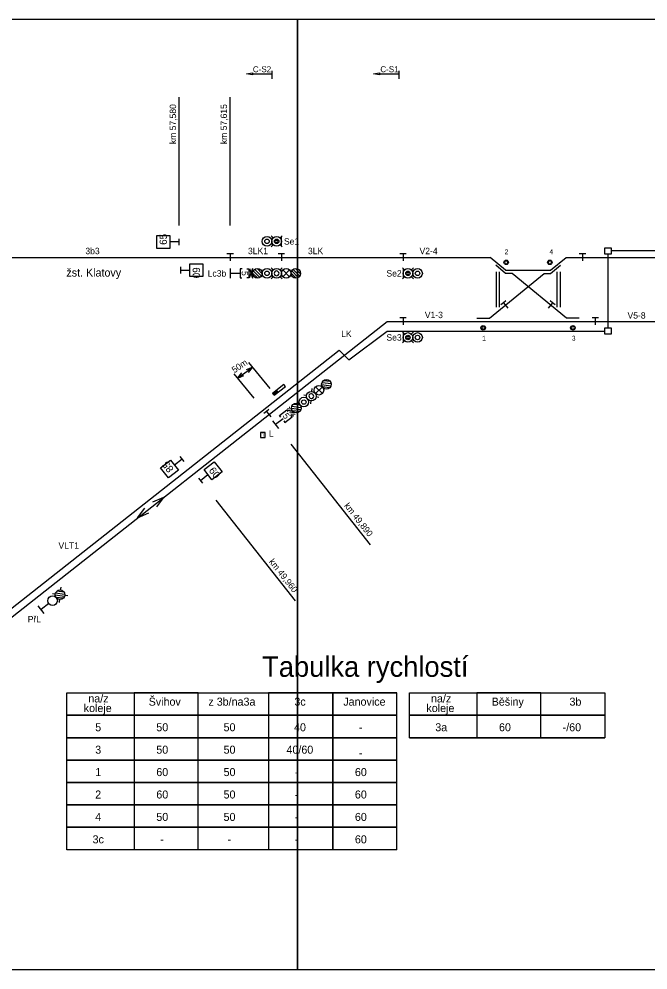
# Model space of a CAD drawing. Extents: x -1146 to 534, y 4 to 301.
# Drawn here: x -602.9 to -406.6, y 4.4 to 301.4 of the extents above; entities that cross this region are included whole.
import ezdxf

# ---------------------------------------------------------------- set-up
doc = ezdxf.new("R2010")
doc.units = 0
for name, color, linetype in [('1', 7, 'Continuous'), ('formát tisku', 7, 'Continuous'), ('kabel', 7, 'Continuous'), ('koleje', 7, 'Continuous'), ('návěstidla', 7, 'Continuous'), ('POPIS', 7, 'Continuous'), ('popisy', 7, 'Continuous'), ('čd', 7, 'Continuous')]:
    doc.layers.add(name, color=color, linetype=linetype)

# ---------------------------------------------------------------- blocks, each defined once
blk = doc.blocks.new('SB1')
for p, q in [((0, 1.08), (-1, 1.08)), ((1, 1.08), (0, 1.08)), ((0, 1.08), (0, -1.08))]:
    blk.add_line(p, q)
blk = doc.blocks.new('NS1')
for p, q in [((-1, 2.5), (-1.7, 3.2)), ((1, 2.5), (1.7, 3.2)), ((-1, 0.5), (-1.7, -0.2)), ((-1.5, 0), (1.5, 0)), ((1, 0.5), (1.7, -0.2))]:
    blk.add_line(p, q)
for centre, radius in [((0, 4.5), 1.5), ((0, 1.5), 1.5), ((0, 4.5), 0.7)]:
    blk.add_circle(centre, radius)
for start, end in [(0, 180), (180, 0)]:
    blk.add_arc((0, 1.5), 0.375, start, end)
blk = doc.blocks.new('NS16')
for p, q in [((-1.499, 0.6437), (-1.1298, 1.0129)), ((-1.4356, 0), (-0.4227, 1.0129)), ((-0.7285, 0), (0.2844, 1.0129)), ((-0.0214, 0), (0.9915, 1.0129)), ((0.6857, 0), (1.499, 0.8133)), ((1.3928, 0), (1.499, 0.1062))]:
    blk.add_line(p, q)
blk = doc.blocks.new('U10')
at = {"layer": '1'}
for p, q in [((-6.9999, -2), (-6.9999, 2)), ((-6.9999, 2), (-3, 2)), ((-3, 2), (-3, -2)), ((0, 0), (-3, 0)), ((0, -1), (0, 1)), ((-3, -2), (-6.9999, -2))]:
    blk.add_line(p, q, dxfattribs=at)
blk = doc.blocks.new('O9')
for p, q in [((-1.5, 3), (-1.5, 0)), ((1.5, 3), (-1.5, 3)), ((-1.5, 0), (1.5, 0)), ((1.5, 0), (1.5, 3))]:
    blk.add_line(p, q)
blk.add_text('T', height=2).set_placement((-0.68, 0.41))
blk = doc.blocks.new('_X11')
for p, q in [((-0.5, 5.16), (0.34, 6)), ((-0.5, 5.33), (0.17, 6)), ((-0.5, 5.51), (-0.01, 6)), ((-0.5, 5.69), (-0.19, 6)), ((-0.5, 5.86), (-0.36, 6)), ((-0.5, 4.98), (0.5, 5.98)), ((-0.5, 4.8), (0.5, 5.8)), ((-0.5, 4.63), (0.5, 5.63)), ((-0.5, 4.45), (0.5, 5.45)), ((-0.5, 4.27), (0.5, 5.27)), ((-0.5, 4.1), (0.5, 5.1)), ((-0.42, 4), (0.5, 4.92)), ((-0.24, 4), (0.5, 4.74)), ((-0.07, 4), (0.5, 4.57)), ((0.11, 4), (0.5, 4.39)), ((0.29, 4), (0.5, 4.21)), ((0.46, 4), (0.5, 4.04))]:
    blk.add_line(p, q)
blk = doc.blocks.new('PZ15')
for p, q in [((0.5, 6), (-0.5, 6)), ((-0.5, 6), (-0.5, 0)), ((0.5, 0), (0.5, 6)), ((-0.5, 0), (0.5, 0))]:
    blk.add_line(p, q)
blk.add_lwpolyline([(0.5, 6), (0.5, 4), (-0.5, 4), (-0.5, 6)], close=True)
blk.add_lwpolyline([(-0.5, 6), (0.5, 6), (0.5, 4), (-0.5, 4), (-0.5, 6)])
blk.add_blockref('_X11', (0, 0))
blk = doc.blocks.new('PZ2')
for start, end in [(0, 180), (180, 0)]:
    blk.add_arc((0, 2), 0.5, start, end)

msp = doc.modelspace()

# ---------------------------------------------------------------- linework, layer by layer
for p, q in [((-515.96, 301.44), (-515.96, 292.56)), ((-537, 223.5), (-537, 220.5)), ((-527.75, 220.7), (-529.8, 222.8)), ((-527.3, 221.2), (-529.3, 223.2)), ((-527, 221.9), (-528.6, 223.5)), ((-523.5, 223), (-524.2, 223.7)), ((-521.5, 223), (-520.8, 223.7)), ((-515.75, 220.7), (-517.78, 222.78)), ((-515.26, 221.16), (-517.34, 223.24)), ((-515, 221.9), (-516.6, 223.5)), ((-534, 222), (-537, 222)), ((-528.4, 220.5), (-530, 222.1)), ((-523.5, 221), (-524.2, 220.3)), ((-521.5, 221), (-520.8, 220.3)), ((-516.4, 220.5), (-518, 222.1)), ((-534.6, 189.34), (-533.37, 190.96)), ((-534.59, 189.32), (-532.73, 190.15)), ((-530.12, 192.64), (-532.02, 191.91)), ((-530.11, 192.63), (-531.43, 191.07)), ((-505.55, 186.82), (-508.46, 187.2)), ((-505.51, 187.49), (-508.31, 187.82)), ((-505.7, 188.22), (-507.95, 188.49)), ((-511.49, 185.07), (-511.37, 186.05)), ((-505.94, 186.26), (-508.18, 186.53)), ((-513.06, 183.83), (-514.04, 183.95)), ((-511.82, 182.26), (-511.94, 181.28)), ((-510.25, 183.5), (-509.27, 183.38)), ((-514.98, 179.39), (-517.89, 179.78)), ((-514.93, 180.06), (-517.74, 180.4)), ((-515.36, 178.83), (-517.61, 179.1)), ((-515.13, 180.8), (-517.38, 181.07)), ((-523.74, 175.95), (-521.89, 173.59)), ((-520.46, 176.62), (-522.82, 174.77)), ((-557.77, 152.06), (-561.21, 150.56)), ((-557.77, 152.06), (-560.04, 149.07)), ((-565.89, 145.67), (-563.62, 148.66)), ((-565.89, 145.67), (-562.45, 147.17)), ((-591.51, 121.81), (-592.49, 121.92)), ((-588.68, 121.76), (-591.49, 122.09)), ((-588.88, 122.49), (-591.13, 122.76)), ((-589.94, 123.04), (-589.82, 124.03)), ((-593.64, 118.86), (-596, 117)), ((-588.73, 121.09), (-591.64, 121.47)), ((-589.11, 120.53), (-591.36, 120.8)), ((-590.27, 120.24), (-590.39, 119.25)), ((-588.7, 121.47), (-587.72, 121.36)), ((-595.07, 115.82), (-596.93, 118.18)), ((-515.96, 4.44), (-515.96, 13.33))]:
    msp.add_line(p, q)
for centre, radius in [((-522.5, 232), 0.7), ((-450.81, 225.44), 0.7), ((-437.19, 225.44), 0.7), ((-528.5, 222), 1.5), ((-525.5, 222), 1.5), ((-522.5, 222), 1.5), ((-519.5, 222), 1.5), ((-516.5, 222), 1.5), ((-525.5, 222), 0.7), ((-481.5, 222), 0.7), ((-458, 205), 0.7), ((-430, 205), 0.7), ((-481.5, 202), 0.7), ((-506.94, 187.37), 1.5), ((-511.66, 183.66), 1.5), ((-509.3, 185.52), 1.5), ((-516.37, 179.95), 1.5), ((-514.01, 181.81), 1.5), ((-514.01, 181.81), 0.7), ((-590.11, 121.64), 1.5), ((-592.46, 119.78), 1.5)]:
    msp.add_circle(centre, radius)
for centre, start, end in [((-522.5, 222), 90, 270), ((-522.5, 222), 270, 90), ((-511.66, 183.66), 128.217, 308.217), ((-511.66, 183.66), 308.217, 128.217)]:
    msp.add_arc(centre, 0.75, start, end)
at = {"layer": 'formát tisku'}
for points in [[(-725.96, 301.44), (-515.96, 301.44), (-515.96, 4.44), (-725.96, 4.44)], [(-515.96, 301.44), (-305.96, 301.44), (-305.96, 4.44), (-515.96, 4.44)]]:
    msp.add_lwpolyline(points, close=True, dxfattribs=at)
at = {"layer": 'kabel'}
msp.add_line((-419, 205), (-419, 228), dxfattribs=at)
for points in [[(-382, 247), (-404, 229), (-418, 229)], [(-736, 105), (-670, 105), (-670, 109), (-616, 109), (-503, 198), (-500, 195), (-488, 204), (-420, 204)]]:
    msp.add_lwpolyline(points, dxfattribs=at)
for points in [[(-420, 230), (-418, 230), (-418, 228), (-420, 228)], [(-420, 205), (-418, 205), (-418, 203), (-420, 203)]]:
    msp.add_lwpolyline(points, close=True, dxfattribs=at)
at = {"layer": 'koleje'}
for p, q in [((-648, 227), (-570.35, 227)), ((-648, 227), (-455.86, 227)), ((-451, 223), (-455.86, 227)), ((-437, 223), (-432.14, 227)), ((-432.14, 227), (-401.21, 227)), ((-451, 222), (-454.09, 224.54)), ((-451, 223), (-437, 223)), ((-437, 222), (-433.91, 224.54)), ((-456, 208), (-439, 222)), ((-454, 222.5), (-454, 211.5)), ((-453, 222.5), (-453, 211.5)), ((-449, 222), (-451, 222)), ((-432, 208), (-449, 222)), ((-439, 222), (-437, 222)), ((-435, 222.5), (-435, 211.5)), ((-434, 222.5), (-434, 211.5)), ((-460, 208), (-456, 208)), ((-428, 208), (-432, 208))]:
    msp.add_line(p, q, dxfattribs=at)
msp.add_lwpolyline([(-736, 107), (-615, 107), (-488, 207), (-304, 207)], dxfattribs=at)
at = {"layer": 'návěstidla'}
for p, q in [((-520.56, 223.06), (-518.44, 220.94)), ((-520.56, 220.94), (-518.44, 223.06)), ((-510.35, 186.58), (-508.22, 184.45)), ((-510.35, 184.45), (-508.22, 186.58))]:
    msp.add_line(p, q, dxfattribs=at)
at = {"layer": 'POPIS'}
msp.add_line((-534.7, 189.3), (-530.11, 192.58), dxfattribs=at)
at = {"layer": 'popisy'}
for p, q in [((-523.88, 282.8), (-523.88, 285.27)), ((-484.25, 282.8), (-484.25, 285.27)), ((-530.05, 284.33), (-523.8, 284.33)), ((-490.42, 284.33), (-484.17, 284.33)), ((-552.89, 237), (-552.89, 277)), ((-537, 237), (-537, 277)), ((-524.55, 186.08), (-531.21, 194.12)), ((-529.55, 183.08), (-535.77, 190.59)), ((-518.03, 168.69), (-493.29, 137.26)), ((-541.5, 151.21), (-516.76, 119.78))]:
    msp.add_line(p, q, dxfattribs=at)
for points in [[(-530.05, 284.64), (-530.05, 284.02), (-531.92, 284.33)], [(-490.42, 284.64), (-490.42, 284.02), (-492.3, 284.33)]]:
    msp.add_lwpolyline(points, close=True, dxfattribs=at)
at = {"layer": 'čd'}
for p, q in [((-533.3, 223.43), (-533.93, 223.43)), ((-533.93, 223.43), (-533.93, 220.58)), ((-531.83, 223.43), (-531.2, 223.43)), ((-531.2, 223.43), (-531.2, 220.58)), ((-530, 223.5), (-531.02, 220.5)), ((-531.01, 223.49), (-530.01, 220.5)), ((-533.93, 220.58), (-533.31, 220.58)), ((-531.2, 220.58), (-531.82, 220.58)), ((-521.59, 177.61), (-519.35, 179.38)), ((-519.35, 179.38), (-518.97, 178.89)), ((-521.2, 177.12), (-521.59, 177.61)), ((-520.29, 175.96), (-519.9, 175.47)), ((-519.9, 175.47), (-517.66, 177.24)), ((-517.66, 177.24), (-518.05, 177.72)), ((-420, 91), (-420, 77)), ((-481, 77), (-420, 77))]:
    msp.add_line(p, q, dxfattribs=at)
for points in [[(-485, 84), (-588, 84), (-588, 91), (-485, 91)], [(-547, 42), (-547, 91), (-567, 91), (-567, 42)], [(-505, 42), (-505, 91), (-525, 91), (-525, 42)], [(-485, 42), (-485, 91), (-505, 91), (-505, 42)], [(-420, 84), (-481, 84), (-481, 91), (-420, 91)], [(-440, 77), (-440, 91), (-460, 91), (-460, 77)], [(-485, 77), (-588, 77), (-588, 84), (-485, 84)], [(-420, 77), (-481, 77), (-481, 84), (-420, 84)], [(-485, 70), (-588, 70), (-588, 77), (-485, 77)], [(-485, 63), (-588, 63), (-588, 70), (-485, 70)], [(-485, 56), (-588, 56), (-588, 63), (-485, 63)], [(-485, 49), (-588, 49), (-588, 56), (-485, 56)], [(-485, 42), (-588, 42), (-588, 49), (-485, 49)]]:
    msp.add_lwpolyline(points, dxfattribs=at)

# ---------------------------------------------------------------- block references
at = {"layer": 'návěstidla'}
for name, p, rotation in [('NS1', (-521, 232), 90), ('NS1', (-483, 222), -90.00000000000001), ('NS1', (-483, 202), -90.00000000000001), ('NS16', (-517.55, 179.02), 128.21695114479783)]:
    msp.add_blockref(name, p, dxfattribs=dict(at, rotation=rotation))
at = {"layer": 'čd'}
for name, p in [('U10', (-552.89, 231.81)), ('SB1', (-537, 227)), ('SB1', (-521, 227)), ('SB1', (-483, 227)), ('SB1', (-427, 227)), ('SB1', (-483, 207)), ('SB1', (-423, 207))]:
    msp.add_blockref(name, p, dxfattribs=at)
for name, p, rotation in [('PZ2', (-452.09, 223.89), -39.4724598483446), ('PZ2', (-435.91, 223.89), 39.472459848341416), ('U10', (-552.56, 223), 179.9999999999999), ('SB1', (-451, 212), 39.47245984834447), ('SB1', (-437, 212), -39.4724598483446), ('PZ2', (-458, 207), 180), ('PZ2', (-430, 207), 180), ('SB1', (-525, 178), 38.216951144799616), ('U10', (-552, 164), 38.216951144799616), ('U10', (-546.29, 157.29), -141.7830488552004)]:
    msp.add_blockref(name, p, dxfattribs=dict(at, rotation=rotation))
at = {"layer": 'čd', "xscale": 0.7500000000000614, "yscale": 0.7500000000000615, "rotation": 128.2169511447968}
msp.add_blockref('PZ15', (-520, 187), dxfattribs=at)
at = {"layer": 'čd', "xscale": 0.5000000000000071, "yscale": 0.5000000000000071}
msp.add_blockref('O9', (-526.82, 170.77), dxfattribs=at)

# ---------------------------------------------------------------- texts
for s, height, p in [('C-S2', 1.875, (-529.92, 284.82)), ('C-S1', 1.875, (-490.12, 284.82)), ('2', 1.5, (-451.32, 228)), ('4', 1.5, (-437.32, 228)), ('1', 1.5, (-458.32, 201)), ('3', 1.5, (-430.32, 201))]:
    msp.add_text(s, height=height).set_placement(p)
msp.add_text('60', height=2.3, rotation=308.217).set_placement((-543.82, 160.37))
at = {"layer": '1'}
for s, rotation, p in [('65', 90, (-556.74, 230.91)), ('60', 270, (-548.71, 223.9)), ('85', 128.217, (-554.48, 160.93))]:
    msp.add_text(s, height=2.3, rotation=rotation, dxfattribs=at).set_placement(p)
at = {"layer": 'popisy'}
for s, rotation, p in [('km 57,580', 90, (-553.89, 262.37)), ('km 57,615', 90, (-538, 262.37)), ('5', 270, (-533.44, 222.75)), ('50m', 34.4327, (-535.66, 190.77)), ('5', 307.615, (-520.73, 177.46)), ('km 49,890', 308.217, (-501.55, 149.38)), ('km 49,960', 308.217, (-525.02, 131.9))]:
    msp.add_text(s, height=2, rotation=rotation, dxfattribs=at).set_placement(p)
for s, height, p in [('Se1', 2, (-520.21, 231)), ('3b3', 2, (-582.21, 228)), ('3LK1', 2, (-531.44, 228)), ('3LK', 2, (-512.72, 228)), ('V2-4', 2, (-477.88, 228)), ('žst. Klatovy', 2.5, (-588.14, 221)), ('Lc3b', 2, (-544.03, 221)), ('Se2', 2, (-488.21, 221)), ('V1-3', 2, (-476.23, 208.03)), ('V5-8', 2, (-412.94, 207.88)), ('LK', 2, (-502.34, 202.11)), ('Se3', 2, (-488.21, 201)), ('L', 2, (-524.9, 171)), ('VLT1', 2, (-590.61, 136)), ('PřL', 2, (-600.21, 113)), ('Tabulka rychlostí', 6.3738, (-527.03, 96)), ('na/z', 2.5, (-581.29, 88)), ('Švihov', 2.5, (-562.45, 87)), ('z 3b/na3a ', 2.5, (-543.8, 87)), ('3c', 2.5, (-516.96, 87)), ('Janovice', 2.5, (-501.68, 87)), ('na/z', 2.5, (-474.29, 88)), ('Běšiny', 2.5, (-455.35, 87)), ('3b', 2.5, (-431.06, 87)), ('koleje', 2.5, (-582.73, 85)), ('koleje', 2.5, (-475.73, 85)), ('5', 2.5, (-579.14, 79)), ('50', 2.5, (-560.06, 79)), ('50', 2.5, (-539.06, 79)), ('40', 2.5, (-517.06, 79)), ('3a', 2.5, (-472.96, 79)), ('60', 2.5, (-453.06, 79)), ('-/60', 2.5, (-433.19, 79)), ('-', 2.5, (-496.83, 79)), ('3', 2.5, (-579.14, 72)), ('50', 2.5, (-560.06, 72)), ('50', 2.5, (-539.06, 72)), ('40/60', 2.5, (-519.42, 72)), ('-', 2.5, (-496.83, 71)), ('1', 2.5, (-579.14, 65)), ('60', 2.5, (-560.06, 65)), ('50', 2.5, (-539.06, 65)), ('-', 2.5, (-516.83, 65)), ('60', 2.5, (-498.06, 65)), ('2', 2.5, (-579.14, 58)), ('60', 2.5, (-560.06, 58)), ('50', 2.5, (-539.06, 58)), ('60', 2.5, (-498.06, 58)), ('-', 2.5, (-516.83, 58)), ('4', 2.5, (-579.14, 51)), ('50', 2.5, (-560.06, 51)), ('50', 2.5, (-539.06, 51)), ('60', 2.5, (-498.06, 51)), ('-', 2.5, (-516.83, 51)), ('3c', 2.5, (-579.96, 44)), ('-', 2.5, (-558.83, 44)), ('-', 2.5, (-537.83, 44)), ('-', 2.5, (-516.83, 44)), ('60', 2.5, (-498.06, 44))]:
    msp.add_text(s, height=height, dxfattribs=at).set_placement(p)

doc.saveas('drawing.dxf')
